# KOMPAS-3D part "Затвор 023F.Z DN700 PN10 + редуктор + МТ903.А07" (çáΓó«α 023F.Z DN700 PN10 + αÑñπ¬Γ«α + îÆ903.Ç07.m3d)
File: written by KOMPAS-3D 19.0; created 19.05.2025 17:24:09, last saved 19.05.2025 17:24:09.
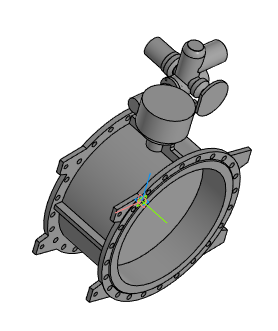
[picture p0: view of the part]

Document properties: Полное имя файла: Затвор 023F.Z DN700 PN10 + редуктор + МТ903.А07.a3d

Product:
- Part/product: Затвор 023F.Z DN700 PN10 + редуктор + МТ903.А07
    Масса: 626.044

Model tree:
1. Операция без истории:1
